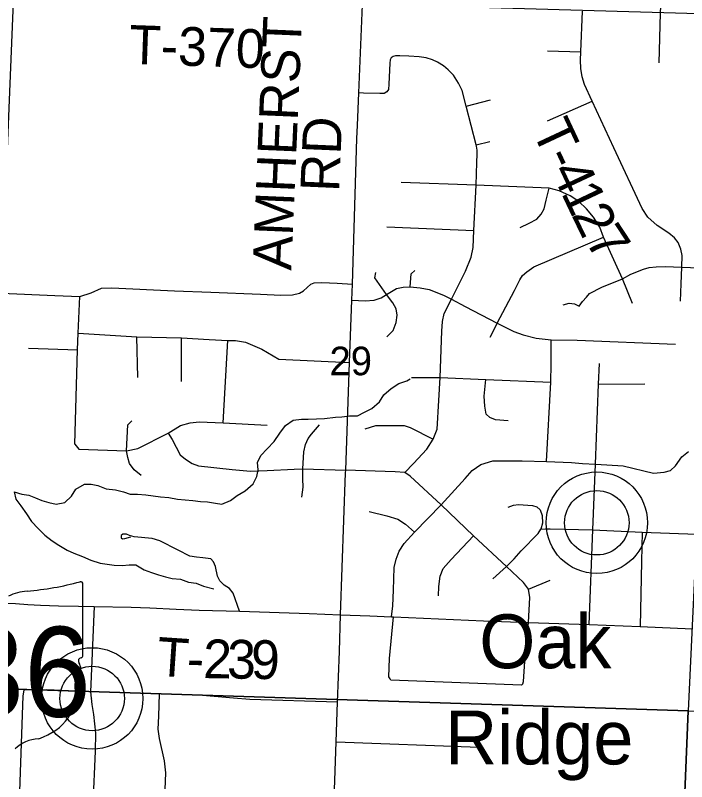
# Model space of a CAD drawing. Extents: x 0 to 34, y 0 to 22.
# Drawn here: x 4.185 to 5.169, y 15.827 to 16.95 of the extents above; entities that cross this region are included whole.
import ezdxf

# ---------------------------------------------------------------- set-up
doc = ezdxf.new("R2010")
doc.units = 0
for name, color, linetype in [('GM_X_Corporation', 7, 'Continuous'), ('GM_X_Minor_River', 7, 'Continuous'), ('GM_X_Section_Text', 7, 'Continuous'), ('GM_X_State_Shield', 7, 'Continuous'), ('GM_X_Township_Road', 7, 'Continuous'), ('GM_X_Township_Road_Text', 7, 'Continuous'), ('GM_X_Unincorporated', 7, 'Continuous'), ('GM_X_Unincorporated_Location', 7, 'Continuous'), ('GM_X_Unincorporated_Text', 7, 'Continuous')]:
    doc.layers.add(name, color=color, linetype=linetype)

msp = doc.modelspace()

# ---------------------------------------------------------------- linework, layer by layer
at = {"layer": 'GM_X_Corporation'}
for points in [[(5.2034, 16.9522), (5.1967, 16.4715), (5.1712, 15.9307), (4.1402, 15.964), (4.1823, 16.9818)], [(4.1402, 15.964), (5.1712, 15.9307), (5.1298, 14.9148), (4.1106, 14.9455)], [(5.1712, 15.9307), (6.2042, 15.8911), (6.1854, 14.88), (5.1298, 14.9148)]]:
    msp.add_lwpolyline(points, close=True, dxfattribs=at)
at = {"layer": 'GM_X_Minor_River'}
for points in [[(4.1828, 16.2517), (4.1942, 16.2483), (4.2045, 16.2469), (4.214, 16.2427), (4.2235, 16.239), (4.2337, 16.236), (4.2443, 16.2337), (4.2572, 16.236), (4.267, 16.2452), (4.2731, 16.2555), (4.2859, 16.2631), (4.2958, 16.2631), (4.3056, 16.2609), (4.3178, 16.256), (4.3315, 16.2549), (4.3432, 16.2515), (4.3531, 16.2482), (4.3637, 16.2482), (4.3759, 16.2475), (4.3865, 16.246), (4.3975, 16.2445), (4.4096, 16.2434), (4.4225, 16.2412), (4.4335, 16.2401), (4.4449, 16.239), (4.4559, 16.2375), (4.4665, 16.2372), (4.4779, 16.2353), (4.4874, 16.2339), (4.5003, 16.2388), (4.5101, 16.2465), (4.5214, 16.253), (4.5335, 16.2636), (4.5388, 16.2743), (4.5406, 16.2838), (4.5398, 16.2948), (4.5447, 16.3051), (4.5541, 16.3146), (4.5643, 16.3253), (4.5726, 16.3378), (4.5809, 16.3488), (4.5922, 16.3565), (4.604, 16.358), (4.6138, 16.3581), (4.626, 16.3585), (4.6381, 16.3593), (4.654, 16.3613), (4.6635, 16.3617), (4.6745, 16.3632), (4.6862, 16.3629), (4.6965, 16.3683), (4.7074, 16.3736), (4.7184, 16.3835), (4.7248, 16.3938), (4.7357, 16.4033), (4.7471, 16.4102), (4.7588, 16.4144), (4.7637, 16.4171)], [(4.1828, 16.2517), (4.1852, 16.2411), (4.1928, 16.2313), (4.2012, 16.2195), (4.2084, 16.2082), (4.218, 16.1979), (4.2279, 16.1881), (4.2385, 16.1798), (4.2484, 16.1734), (4.2606, 16.1662), (4.2705, 16.1617), (4.283, 16.1568), (4.2955, 16.1515), (4.3092, 16.1474), (4.3293, 16.1445), (4.3411, 16.1437), (4.3517, 16.1449), (4.3612, 16.1446), (4.3737, 16.1374), (4.3843, 16.1336), (4.3946, 16.1303), (4.4048, 16.1273), (4.4147, 16.1246), (4.4269, 16.1236), (4.4386, 16.1194), (4.45, 16.1179), (4.4603, 16.1134), (4.4755, 16.1097)]]:
    msp.add_lwpolyline(points, dxfattribs=at)
at = {"layer": 'GM_X_State_Shield'}
for q in [(4.2836, 16.1166), (4.2836, 16.012)]:
    msp.add_line((4.2836, 16.012), q, dxfattribs=at)
for centre, major_axis, start_param, end_param in [((4.1662, 16.3845), (0.3495, 0), 4.814394, 5.042369), ((4.2799, 16.1171), (0.00367, 0), 6.141152, 7.989035), ((4.2108, 16.0506), (0.0703, 0), 1.699011, 2.107814), ((4.2797, 16.0116), (0.00393, 0), 5.05454, 6.418171), ((4.2827, 16.0043), (0.00568, 0), 1.883978, 3.671073), ((4.2466, 15.991), (0.0341, 0), 5.934695, 6.695948), ((4.2967, 15.9681), (0.0248, 0), 2.387724, 3.262537), ((4.1858, 15.9548), (0.0874, 0), 5.101752, 6.440018), ((4.2226, 15.8519), (0.0479, 0), 1.647645, 2.488434)]:
    msp.add_ellipse(centre, major_axis=major_axis, ratio=0.8, start_param=start_param, end_param=end_param, dxfattribs=at)
at = {"layer": 'GM_X_Township_Road'}
for p, q in [((4.9647, 16.8976), (5.0136, 16.8961)), ((4.8458, 16.8168), (4.8815, 16.826)), ((4.9651, 16.7954), (5.0302, 16.8241)), ((4.8603, 16.76), (4.8805, 16.7651)), ((4.7293, 16.6399), (4.857, 16.6344)), ((4.3642, 16.4191), (4.3629, 16.479)), ((4.4284, 16.4134), (4.4282, 16.4775)), ((4.4894, 16.3526), (4.4963, 16.4736)), ((4.2041, 16.462), (4.276, 16.4597)), ((5.0399, 16.4096), (5.1076, 16.4099)), ((4.6616, 16.0717), (4.6689, 16.2797)), ((4.937, 16.109), (4.9686, 16.1223)), ((4.9266, 15.9687), (4.7354, 15.9759)), ((4.6552, 15.8855), (4.8645, 15.8775))]:
    msp.add_line(p, q, dxfattribs=at)
for points in [[(4.6689, 16.2797), (4.669, 16.2837), (4.6747, 16.4412), (4.6781, 16.5323), (4.6789, 16.5559), (4.6855, 16.7695), (4.6863, 16.7882), (4.6883, 16.8362), (4.6935, 16.965), (4.703, 17.1804), (4.7036, 17.2213), (4.7087, 17.341), (4.7128, 17.4329), (4.7206, 17.6059)], [(5.1285, 16.8801), (5.1308, 16.953), (5.1357, 17.0606), (5.136, 17.0685), (5.1373, 17.0771), (5.1388, 17.0839), (5.1413, 17.091), (5.1439, 17.097), (5.1488, 17.1057), (5.1552, 17.1143), (5.1616, 17.1237), (5.1728, 17.1318)], [(5.1598, 16.5311), (5.1608, 16.5566), (5.1619, 16.5811), (5.1623, 16.598), (5.1606, 16.6074), (5.1564, 16.6169), (5.1513, 16.6239), (5.1426, 16.6309), (5.1255, 16.6419), (5.1122, 16.6539), (5.1037, 16.6669), (5.0622, 16.7555), (5.0302, 16.8241), (5.0193, 16.8485), (5.0157, 16.8598), (5.0138, 16.8721), (5.0134, 16.884), (5.0136, 16.8961), (5.0163, 16.9558)], [(4.7557, 16.2799), (4.7682, 16.2932), (4.788, 16.3144), (4.7974, 16.329), (4.803, 16.3435), (4.8054, 16.3857), (4.8075, 16.4191), (4.8099, 16.4873), (4.8108, 16.5012), (4.8132, 16.5132), (4.8243, 16.5339), (4.8445, 16.5748), (4.8531, 16.5954), (4.856, 16.6099), (4.857, 16.6344), (4.8603, 16.7012), (4.8613, 16.7344), (4.8618, 16.7465), (4.8616, 16.7506), (4.8616, 16.7525), (4.8613, 16.7553), (4.8607, 16.7581), (4.8603, 16.76), (4.8458, 16.8168), (4.8396, 16.8396), (4.8346, 16.8506), (4.8269, 16.8619), (4.8191, 16.8701), (4.8123, 16.8756), (4.8035, 16.881), (4.7961, 16.8844), (4.7869, 16.8873), (4.7768, 16.8892), (4.7618, 16.89), (4.7483, 16.8905), (4.7418, 16.8906), (4.7384, 16.8894), (4.7358, 16.8873), (4.7343, 16.8848), (4.7335, 16.8796), (4.7324, 16.8488), (4.7316, 16.8412), (4.7292, 16.8375), (4.7252, 16.8353), (4.7189, 16.8351), (4.695, 16.836), (4.6883, 16.8362)], [(5.0469, 16.625), (5.0416, 16.6394), (5.0323, 16.6543), (5.0219, 16.6664), (5.0106, 16.6771), (4.9979, 16.6856), (4.9821, 16.6928), (4.9675, 16.6968), (4.8603, 16.7012), (4.7505, 16.7051)], [(4.9246, 16.639), (4.9379, 16.6454), (4.9492, 16.6513), (4.9554, 16.6584), (4.96, 16.6662), (4.963, 16.6788), (4.9675, 16.6968)], [(4.881, 16.4782), (4.8869, 16.4896), (4.8912, 16.4986), (4.9165, 16.5468), (4.9243, 16.5621), (4.9284, 16.5685), (4.9348, 16.5742), (4.9449, 16.5814), (5.0469, 16.625)], [(5.0894, 16.5275), (5.0748, 16.564), (5.0469, 16.625)], [(4.7286, 16.5406), (4.7118, 16.5653), (4.7131, 16.573)], [(4.7637, 16.5521), (4.7648, 16.571), (4.7705, 16.5761)], [(5.0114, 16.5239), (5.0161, 16.5306), (5.0223, 16.5369), (5.0265, 16.5422), (5.0444, 16.5518), (5.0748, 16.564), (5.0872, 16.5705), (5.1058, 16.578), (5.1139, 16.5802), (5.1241, 16.5814), (5.1375, 16.5817), (5.1619, 16.5811), (5.2381, 16.5778)], [(4.1643, 16.5428), (4.2425, 16.5394), (4.2791, 16.5377), (4.2956, 16.5434), (4.3111, 16.5503), (4.326, 16.5507), (4.4178, 16.5461), (4.4715, 16.5444), (4.544, 16.5411), (4.574, 16.5396), (4.5912, 16.5402), (4.6014, 16.5427), (4.607, 16.5464), (4.618, 16.556), (4.6227, 16.5577), (4.6342, 16.5585), (4.6563, 16.5575), (4.6789, 16.5559)], [(4.6781, 16.5323), (4.6978, 16.5313), (4.7109, 16.5323), (4.7208, 16.5358), (4.7286, 16.5406), (4.7437, 16.5496), (4.7531, 16.5517), (4.7637, 16.5521), (4.7781, 16.5504), (4.7915, 16.5481), (4.8124, 16.54), (4.8243, 16.5339), (4.844, 16.5232), (4.8912, 16.4986), (4.9156, 16.4865), (4.9292, 16.4816), (4.9481, 16.4767), (4.9705, 16.4743), (5.0085, 16.4737), (5.1526, 16.4682)], [(4.2718, 16.3218), (4.276, 16.4597), (4.277, 16.4843), (4.2791, 16.5377)], [(4.7295, 16.4786), (4.7384, 16.4879), (4.7429, 16.4998), (4.7444, 16.5103), (4.7429, 16.52), (4.7382, 16.5287), (4.7286, 16.5406)], [(4.988, 16.5258), (4.9966, 16.5279), (5.0046, 16.5273), (5.0114, 16.5239)], [(4.277, 16.4843), (4.3629, 16.479), (4.4282, 16.4775), (4.469, 16.4749), (4.4963, 16.4736), (4.5075, 16.4732), (4.5221, 16.4708), (4.5461, 16.4607), (4.5712, 16.4463), (4.6747, 16.4412)], [(4.9634, 16.2963), (4.9698, 16.4125), (4.9701, 16.4386), (4.9705, 16.4743)], [(5.0261, 16.0572), (5.0315, 16.1959), (5.0352, 16.2923), (5.0399, 16.4096), (5.0412, 16.4397)], [(4.7655, 16.4193), (4.8075, 16.4191), (4.8747, 16.4162), (4.9698, 16.4125)], [(4.9071, 16.3559), (4.8885, 16.3572), (4.8801, 16.3605), (4.8748, 16.3654), (4.8731, 16.3772), (4.8722, 16.3919), (4.8747, 16.4162)], [(4.2718, 16.3218), (4.2776, 16.3142), (4.3477, 16.3116), (4.3644, 16.315), (4.4086, 16.3378), (4.4269, 16.3487), (4.441, 16.3526), (4.4543, 16.3541), (4.4894, 16.3526), (4.5541, 16.3493)], [(4.3691, 16.2755), (4.3589, 16.2841), (4.3521, 16.2933), (4.3495, 16.3022), (4.3477, 16.3116), (4.3495, 16.3501), (4.3555, 16.3558)], [(4.6049, 16.2439), (4.6068, 16.2584), (4.6064, 16.2706), (4.6064, 16.2856), (4.6074, 16.3101), (4.6099, 16.3209), (4.6138, 16.3298), (4.6189, 16.3363), (4.6307, 16.3498)], [(4.6975, 16.3438), (4.713, 16.3491), (4.7549, 16.3487), (4.7634, 16.346), (4.7974, 16.329)], [(4.4086, 16.3378), (4.4145, 16.3283), (4.4263, 16.306), (4.4341, 16.2994), (4.4437, 16.2934), (4.4534, 16.29), (4.5024, 16.2843), (4.5295, 16.2822), (4.5541, 16.2828), (4.5935, 16.2849), (4.6064, 16.2856), (4.669, 16.2837)], [(4.736, 16.0686), (4.7381, 16.0845), (4.739, 16.1077), (4.74, 16.1407), (4.7428, 16.1531), (4.7475, 16.1647), (4.7547, 16.1759), (4.7697, 16.1925), (4.8089, 16.2329), (4.8441, 16.2712), (4.8546, 16.283), (4.8671, 16.2916), (4.8849, 16.2972), (4.9279, 16.2972), (4.9634, 16.2963), (5.0001, 16.2946), (5.0163, 16.2934), (5.0352, 16.2923), (5.0359, 16.2923), (5.0758, 16.29), (5.1205, 16.2792), (5.1358, 16.2804), (5.1453, 16.283), (5.1524, 16.2897), (5.1619, 16.3032), (5.1718, 16.3106)], [(4.9266, 15.9687), (4.9289, 15.9706), (4.9296, 15.9737), (4.9323, 16.0105), (4.9372, 16.0603), (4.9388, 16.0971), (4.937, 16.109), (4.9295, 16.1189), (4.905, 16.1424), (4.8564, 16.1874), (4.8089, 16.2329), (4.7633, 16.2748), (4.7557, 16.2799), (4.7415, 16.281), (4.7121, 16.2822), (4.669, 16.2837)], [(4.9072, 16.2293), (4.9149, 16.2324), (4.9224, 16.2333), (4.9429, 16.2318), (4.9493, 16.2299), (4.9541, 16.2255), (4.9572, 16.217), (4.9576, 16.2058), (4.955, 16.1972)], [(4.7035, 16.2227), (4.7291, 16.2165), (4.7453, 16.2118), (4.7565, 16.2046), (4.7697, 16.1925)], [(4.5131, 16.0767), (4.5041, 16.1033), (4.4984, 16.1099), (4.4908, 16.1151), (4.4844, 16.1215), (4.4811, 16.1281), (4.478, 16.1425), (4.4754, 16.1492), (4.4714, 16.1535), (4.4595, 16.1552), (4.4502, 16.1561), (4.4405, 16.1574), (4.4235, 16.1661), (4.3964, 16.18), (4.3851, 16.1833), (4.3587, 16.1859), (4.3522, 16.1878), (4.3478, 16.1895), (4.3424, 16.1896), (4.3399, 16.1879), (4.3398, 16.1845), (4.3417, 16.1829), (4.3452, 16.1834), (4.3541, 16.1857)], [(4.8845, 16.1241), (4.905, 16.1424), (4.916, 16.1538), (4.9265, 16.1653), (4.951, 16.1905), (4.955, 16.1972), (4.9619, 16.1976), (4.9689, 16.1973), (5.0315, 16.1959), (5.1039, 16.1925), (5.184, 16.1896)], [(5.1039, 16.1925), (5.1026, 16.1497), (5.1006, 16.0545)], [(4.8049, 16.0995), (4.8055, 16.1128), (4.8077, 16.1282), (4.8118, 16.1394), (4.8236, 16.1528), (4.8564, 16.1874)], [(4.1199, 16.0878), (4.1661, 16.0886), (4.1847, 16.088), (4.2029, 16.0866), (4.2216, 16.0857), (4.2477, 16.0847), (4.2773, 16.084), (4.3004, 16.0838), (4.3544, 16.0828), (4.3818, 16.0818), (4.4203, 16.08), (4.454, 16.0785), (4.5131, 16.0767), (4.6153, 16.0736), (4.6616, 16.0717), (4.7043, 16.07), (4.736, 16.0686), (4.7389, 16.0685), (4.871, 16.0627), (4.9372, 16.0603), (5.0261, 16.0572), (5.1006, 16.0545), (5.1776, 16.0509)], [(4.3004, 16.0838), (4.295, 15.9588), (4.2967, 15.94), (4.2994, 15.9255), (4.3023, 15.8983), (4.3016, 15.872), (4.2985, 15.7937), (4.2973, 15.7528)], [(4.6309, 15.1899), (4.6318, 15.2116), (4.6338, 15.2798), (4.6383, 15.4069), (4.6403, 15.4663), (4.6419, 15.5292), (4.6443, 15.5862), (4.6465, 15.6458), (4.6552, 15.8855), (4.6571, 15.9438), (4.6597, 16.018), (4.6616, 16.0717)], [(4.7354, 15.9759), (4.7342, 15.9778), (4.7323, 15.9805), (4.7332, 16.0074), (4.7389, 16.0685)], [(4.1895, 15.7571), (4.196, 15.9531), (4.1976, 15.9612)], [(4.6571, 15.9438), (4.5286, 15.9474), (4.5045, 15.9495), (4.459, 15.9533), (4.3961, 15.9558), (4.295, 15.9588), (4.2306, 15.9615), (4.1976, 15.9612)], [(4.4016, 15.7443), (4.4041, 15.8155), (4.4053, 15.8403), (4.4035, 15.8578), (4.3959, 15.8904), (4.3941, 15.9038), (4.3949, 15.9233), (4.3961, 15.9558)]]:
    msp.add_lwpolyline(points, dxfattribs=at)
at = {"layer": 'GM_X_Unincorporated'}
for centre, radius in [((5.0372, 16.2064), 0.0744), ((5.0372, 16.2064), 0.0472), ((4.2973, 15.949), 0.0744), ((4.2973, 15.949), 0.0472)]:
    msp.add_circle(centre, radius, dxfattribs=at)
at = {"layer": 'GM_X_Unincorporated_Location'}
for p, q in [((5.0372, 16.2064), (5.0372, 16.2064)), ((4.2973, 15.949), (4.2973, 15.949))]:
    msp.add_line(p, q, dxfattribs=at)

# ---------------------------------------------------------------- texts
at = {"layer": 'GM_X_Section_Text'}
msp.add_text('29', height=0.04186, rotation=0, dxfattribs=at).set_placement((4.6453, 16.4225))
at = {"layer": 'GM_X_State_Shield'}
msp.add_text('236', height=0.13184, dxfattribs=at).set_placement((4.0014, 15.9222))
at = {"layer": 'GM_X_Township_Road_Text'}
for s, height, rotation, p in [('AMHERST', 0.05682, 87.5538, (4.5892, 16.5756)), ('T-370', 0.05682, 358.0341, (4.3508, 16.8789)), ('RD', 0.05682, 87.5449, (4.6592, 16.6905)), ('T', 0.0568, 295.0891, (4.9414, 16.7815)), ('-', 0.0568, 295.0896, (4.9594, 16.743)), ('4', 0.0568, 295.1314, (4.9694, 16.7218)), ('1', 0.0568, 295.329, (4.9843, 16.69)), ('2', 0.0568, 295.8217, (4.9995, 16.6578)), ('7', 0.0568, 303.333, (5.0188, 16.6193)), ('T', 0.0568, 356.1745, (4.3908, 15.9825)), ('2', 0.0568, 359.024, (4.4596, 15.9789)), ('3', 0.0568, 359.1958, (4.4948, 15.9783)), ('9', 0.0568, 359.2157, (4.5298, 15.9778)), ('-', 0.0568, 358.3126, (4.4355, 15.9796))]:
    msp.add_text(s, height=height, rotation=rotation, dxfattribs=at).set_placement(p)
at = {"layer": 'GM_X_Unincorporated_Text'}
for s, p in [('Oak', (4.8649, 15.9933)), ('Ridge', (4.8149, 15.8524))]:
    msp.add_text(s, height=0.07898, rotation=0, dxfattribs=at).set_placement(p)

doc.saveas('drawing.dxf')
